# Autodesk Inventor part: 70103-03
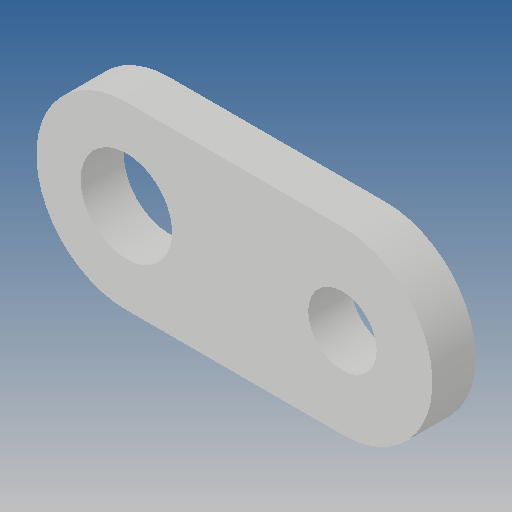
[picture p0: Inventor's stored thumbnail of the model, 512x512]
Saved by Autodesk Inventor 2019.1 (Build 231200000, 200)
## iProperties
Created: 2012-10
Part Number: 70103-03
Material: Ogólny
Document SubType Name: Modeling
Designer: CADENGINEERING4
Density: 1 g/cm^3
Appearance: Domyślna
Author: CADENGINEERING4
Revision Number: ÈÎºÎ
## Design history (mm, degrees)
feature "À­Éì1"
node "Bryła1"
